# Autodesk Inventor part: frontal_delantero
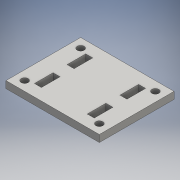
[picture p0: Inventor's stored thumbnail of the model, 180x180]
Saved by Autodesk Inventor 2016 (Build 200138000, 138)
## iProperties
Created: 2017-06
Part Number: frontal_delantero
Material: Generic
Document SubType Name: Modeling
Designer: laboratorioesan
Density: 1 g/cm^3
Appearance: Default
Author: laboratorioesan
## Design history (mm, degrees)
sketch "Sketch1"
  geometry: L1 (0, 0)-(40, 0); L2 (40, 0)-(40, 32); L3 (40, 32)-(0, 32); L4 (0, 32)-(0, 0); L5 (10.175, 22.85)-(29.825, 22.85); L6 (29.825, 22.85)-(29.825, 9.15); L7 (29.825, 9.15)-(10.175, 9.15); L8 (10.175, 9.15)-(10.175, 22.85); L9 (10.175, 27)-(7.175, 27); L10 (7.175, 27)-(7.175, 19); L11 (7.175, 19)-(10.175, 19); L12 (10.175, 19)-(10.175, 27); L13 (10.175, 5)-(7.175, 5); L14 (7.175, 5)-(7.175, 13); L15 (7.175, 13)-(10.175, 13); L16 (10.175, 13)-(10.175, 5); L17 (29.825, 27)-(32.825, 27); L18 (32.825, 27)-(32.825, 19); L19 (32.825, 19)-(29.825, 19); L20 (29.825, 19)-(29.825, 27); L21 (29.825, 13)-(32.825, 13); L22 (32.825, 13)-(32.825, 5); L23 (32.825, 5)-(29.825, 5); L24 (29.825, 5)-(29.825, 13); C1 r 1.5 at (4, 28); C2 r 1.5 at (4, 4); C3 r 1.5 at (36, 4); C4 r 1.5 at (36, 28); 4 further points
  constraints: 48 end point, 12 parallel, 6 horizontal, 6 perpendicular, 4 centre point, 4 midpoint, 4 vertical alignment, 3 horizontal alignment, 3 point on line
  dimensions: "d0" = 40 distance of L3.end L2.end; "d1" = 32 distance of L2.end L1.end; "d2" = 19.65 distance of L6.end L7.end; "d3" = 13.7 distance of L5.end L6.end; "d4" = 3 distance of L11.end L10.end; "d5" = 8 distance of L10.end L9.end; "d6" = 3 distance of L14.end L15.end; "d7" = 8 distance of L13.end L14.end; "d8" = 5 distance from line of L3 L9.end; "d9" = 5 vertical distance of L1.start L13.end; "d10" = 3 distance of L18.end L19.end; "d11" = 3 diameter of C1; "d12" = 3 diameter of C2; "d13" = 3 diameter of C3; "d14" = 3 diameter of C4; "d15" = 4 horizontal distance of L2.end C4.centre; "d16" = 4 horizontal distance of L3.end C1.centre; "d17" = 4 horizontal distance of L3.end C1.centre; "d18" = 4 horizontal distance of L1.start C2.centre
extrude "Extrusion1" new body sketch "Sketch1" distance "d19" = 3; taper "d20" = 0 deg
body "Solid1"
